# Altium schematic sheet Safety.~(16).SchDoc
size A
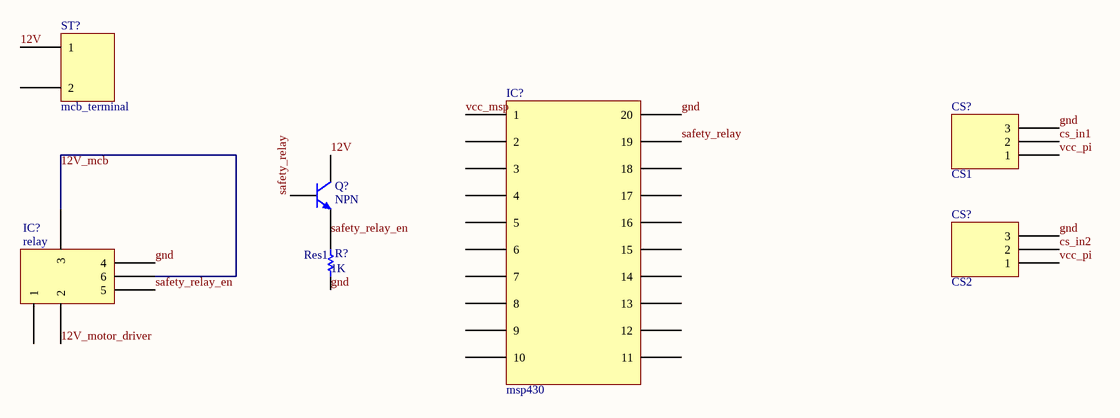
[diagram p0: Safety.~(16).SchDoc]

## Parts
(Parts that share a designator on the sheet are numbered #1, #2 ... from top to bottom, then left to right.)
CS?#1  CS1  [ACS712]
CS?#2  CS2  [ACS712]
IC?#1  msp430  [msp430]
IC?#2  relay  [relay JQX 15F]
Q?  NPN  [TO-226-AA]
R?  Res1  value 1K  [AXIAL-0.3]
ST?  mcb_terminal  [screw_terminal_5]

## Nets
12V: Q?.1(C) ST?.1
12V_mcb: IC?#2.3 IC?#2.6
12V_motor_driver: IC?#2.2
cs_in1: CS?#1.2
cs_in2: CS?#2.2
gnd: CS?#1.3 CS?#2.3 IC?#1.20 IC?#2.4 R?.1
safety_relay: IC?#1.19 Q?.2(B)
safety_relay_en: IC?#2.5 Q?.3(E) R?.2
vcc_msp: IC?#1.1
vcc_pi: CS?#1.1 CS?#2.1

Not connected (* = marked no-connect by the designer): IC?#1 2 3 4 5 6 7 8 9 10 11 12 13 14 15 16 17 18; IC?#2 1; ST? 2

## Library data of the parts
CS?#1 CS?#2 = ACS712
IC?#2 = relay JQX-15F
Q? = NPN: NPN Bipolar Transistor
R? = Res1: Resistor
ST? = screw_terminal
